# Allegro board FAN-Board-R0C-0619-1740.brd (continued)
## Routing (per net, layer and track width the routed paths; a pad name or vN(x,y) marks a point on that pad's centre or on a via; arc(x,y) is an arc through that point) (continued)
FAN2R_SENSOR: length 76.6
  TOP w0.203: BGA1.N7 v2(153.32,20.74) ; R23.2 v3(106.14,30.78)
  BOTTOM w0.203: v2(153.32,20.74) 149.9,24.16 137.52,24.16 132.44,19.08 120.24,19.08 117.73,21.59 98.42,21.59 97.61,22.41 97.61,24.31 100.14,26.85 104.32,26.85 106.67,29.2 v1(106.67,30.18) 106.67,30.25 v3(106.14,30.78)
FAN2R_SENSOR_R: length 25.3
  TOP w0.203: CONN5.1 105.4,34.49 106.13,33.76 v3(106.13,33.04) 106.14,33.03 R23.1 R24.1 ; U4.C1 v3(95.43,23.61)
  BOTTOM w0.203: v3(95.43,23.61) v1(95.43,24.4) 98.44,27.41 103.84,27.41 105.56,29.13 105.56,32.47 v3(106.13,33.04)
FAN3_DET: length 109.5
  TOP w0.152: BGA1.R10 150.14,22.33 150.14,23.37
  TOP w0.203: 150.14,23.37 150.14,23.65 149.22,24.56 142.1,24.56 134.28,16.74 98.25,16.74 87.36,27.62 56.2,27.62 53.96,29.86 v3(53.96,30.77) R10.2
  BOTTOM w0.203: v1(53.17,30.77) 53.95,30.77 v3(53.96,30.77)
FAN3_DET_R: length 36.2
  TOP w0.203: R114.1 R10.1 v3(53.96,33.08) ; U10.C1 v3(41.33,23.17)
  BOTTOM w0.203: v3(41.33,23.17) v1(41.33,23.98) 41.33,25.85 37.08,30.1 37.08,32.05 37.29,32.26 53.13,32.26 v3(53.96,33.08) 54.68,33.81 CONN4.16
FAN3_DIR: length 114.4
  TOP w0.203: BGA1.P10 v2(150.13,21.54) ; R9.2 v3(47.04,30.79)
  BOTTOM w0.203: v3(47.04,30.79) 47.35,31.1 v1(49.52,31.1) 53.36,27.25 53.36,24.49 58.67,19.18 118.07,19.18 119.61,17.64 133.21,17.64 138.43,22.86 148.81,22.86 v2(150.13,21.54)
FAN3_DIR_R: length 17.5
  TOP w0.203: U10.C2 43.23,28.24 45.59,30.61 45.59,32.13 45.83,32.37 R110.1 R9.1 v3(47.04,33.05)
  BOTTOM w0.203: v1(47.83,33.05) 47.04,33.05 v3(47.04,33.05) 47.06,33.07 CONN4.13
FAN3_IN_PWM: length 18.4
  TOP w0.203: U12.C2 v3(39.75,24.89) 39.75,25.52 39.75,25.53 39.75,26.42 43.62,30.29 44.44,30.29 45.09,30.94 45.09,32.16 44.88,32.37 R22.2 44.5,38.42 CONN4.4
  BOTTOM w0.203: v1(39.75,25.7) v3(39.75,24.89)
FAN3_LED_G: length 154.1
  TOP w0.152: BGA1.P11 149.33,21.54 149.33,23.01 148.97,23.37
  TOP w0.203: R1.2 11.68,34.04 v3(12.45,33.27) 20.04,25.68 30.39,25.68 38.54,17.53 57.22,17.53 58.82,15.93 134.97,15.93 142.79,23.75 148.59,23.75 148.97,23.37
  BOTTOM w0.203: v1(13.97,32.51) 13.21,32.51 v3(12.45,33.27)
FAN3_LED_G_R: length 4.2
  TOP w0.203: R1.1 11.77,37.17 v3(11.77,38.1) LED1.C2
  BOTTOM w0.203: v1(11.94,37.08) 11.94,37.94 v3(11.77,38.1)
FAN3_LED_R: length 152.9
  TOP w0.203: BGA1.T11 149.74,22.76 149.74,23.21 148.79,24.16 142.5,24.16 134.67,16.33 58.99,16.33 57.39,17.93 38.96,17.93 30.35,26.54 21.46,26.54 v3(13.72,34.29) ; R5.2 v3(9.65,34.29)
  BOTTOM w0.203: v3(13.72,34.29) v1(12.7,34.29) v3(9.65,34.29)
FAN3_LED_R_R: length 5
  TOP w0.203: R5.1 10.02,37.46 v3(10.02,38.1) LED1.C1
  BOTTOM w0.203: v1(9.91,37.08) 9.91,37.98 v3(10.02,38.1)
FAN3_OUT_PWM: length 17.2
  TOP w0.203: U12.C1 v3(37.85,24.89) 37.85,26.55 41.49,30.19 41.49,32.03 41.83,32.37 R21.2 42.09,32.99 41.98,33.09 CONN4.3
  BOTTOM w0.203: v1(37.85,25.7) v3(37.85,24.89)
FAN3_PWM: length 123.6
  TOP w0.203: v3(42.09,30.78) R21.1 R22.1 ; BGA1.M9 v2(150.93,19.94)
  BOTTOM w0.203: v3(42.09,30.78) v1(42.65,31.34) 43.14,31.84 50.12,31.84 54.58,27.38 54.58,26.41 56.86,24.13 58.9,24.13 62.46,20.57 117.54,20.57 119.95,18.16 132.96,18.16 135.37,20.57 135.39,20.57 138.11,23.29 149.17,23.29 150.93,21.54 v2(150.93,19.94)
FAN3_SENSOR: length 120.4
  TOP w0.203: v3(39.83,30.78) R19.2 ; BGA1.N10 v2(150.13,20.74)
  BOTTOM w0.203: v3(39.83,30.78) v1(39.83,29.99) 41.43,28.4 48.37,28.4 53.59,23.18 53.59,21.65 56.48,18.77 117.9,18.77 119.44,17.23 133.58,17.23 137.12,20.78 146.94,20.78 147.47,21.31 149.56,21.31 v2(150.13,20.74)
FAN3_SENSOR_R: length 18.1
  TOP w0.203: R19.1 R20.1 ; R19.1 39.83,32.91 39.44,33.3 CONN4.2 ; R19.1 39.54,32.37 39.28,32.11 39.28,28.93 36.24,25.89 v3(36.24,24.89) U11.C2
  BOTTOM w0.203: v1(36.24,25.7) v3(36.24,24.89)
FAN3_VCP: length 3.7
  TOP w0.203: U1.4 64.03,25.71 C8.2 v3(65.33,25.09)
  BOTTOM w0.203: v1(64.52,25.09) v3(65.33,25.09)
FAN3R_SENSOR: length 121.6
  TOP w0.203: BGA1.M11 v2(149.33,19.94) ; R17.2 v3(37.63,30.78)
  BOTTOM w0.203: v3(37.63,30.78) 37.63,30.66 v1(38.17,30.12) 40.45,27.84 47.85,27.84 51.99,23.7 51.99,21.22 54.85,18.36 117.74,18.36 119.37,16.73 134.46,16.73 137.06,19.33 148.72,19.33 v2(149.33,19.94)
FAN3R_SENSOR_R: length 18
  TOP w0.203: R17.1 R18.1 ; R17.1 37.63,33.72 36.9,34.45 CONN4.1 ; R17.1 37.47,32.37 37.09,31.99 37.09,29.09 34.34,26.34 v3(34.34,24.89) U11.C1
  BOTTOM w0.203: v1(34.34,25.7) v3(34.34,24.89)
FAN4_DET: length 116.2
  TOP w0.203: R16.2 v3(259.41,30.79) ; BGA1.N3 v2(156.52,20.74)
  BOTTOM w0.203: v3(259.41,30.79) 259.39,30.79 258.57,29.97 v1(252.48,29.97) 249.43,29.97 239.49,20.03 211.92,20.03 204.4,27.55 194.61,27.55 187.5,20.45 165.54,20.45 163.51,22.48 160.4,22.48 158.88,20.95 156.74,20.95 v2(156.52,20.74)
FAN4_DET_R: length 33.3
  TOP w0.203: U13.C1 v3(239.35,20.87) ; R115.1 R16.1 v3(259.41,33.05)
  BOTTOM w0.203: v3(239.35,20.87) v1(240.05,21.57) 249.09,30.61 251.76,30.61 253.01,31.85 258.21,31.85 v3(259.41,33.05) 260.18,33.83 CONN7.16
FAN4_DIR: length 106.1
  TOP w0.152: 157.95,18.35 155.73,18.35 BGA1.K4
  TOP w0.203: 157.95,18.35 168.49,18.35 171.42,15.42 205.43,15.42 215.74,25.73 244.32,25.73 249.35,30.76 251.17,30.76 v3(251.88,31.46) R15.2
  BOTTOM w0.203: v3(251.88,31.46) 251.52,31.82 v1(251.16,31.82)
FAN4_DIR_R: length 26.5
  TOP w0.203: v3(252.57,33.05) R15.1 R111.1 253.86,32.37 254,32.23 254,30.48 253.75,30.23 249.72,30.23 U13.C2
  BOTTOM w0.203: v1(251.77,33.05) v3(252.57,33.05) 252.56,33.05 CONN7.13
FAN4_IN_PWM: length 25
  TOP w0.203: R40.2 v3(250,33.04) 250.02,33.07 CONN7.4 ; U15.C2 v3(237.74,20.85)
  BOTTOM w0.203: v3(250,33.04) 250,32.45 241.05,23.5 239.78,23.5 238.3,22.02 v1(238.3,21.41) v3(237.74,20.85)
FAN4_LED_G: length 73.2
  TOP w0.152: 157.93,20.76 157.31,20.76 BGA1.P2
  TOP w0.203: v1(217.42,35.56) v3(217.42,34.54) 217.42,31.9 203.47,17.95 172.22,17.95 168.26,21.91 159.08,21.91 157.93,20.76
  BOTTOM w0.203: v1(217.42,35.56) v3(217.42,34.54)
FAN4_LED_G_R: length 4.3
  TOP w0.203: v1(217.42,37.08) 217.27,37.23 v3(217.27,38.1) LED4.C2
  BOTTOM w0.203: v1(217.42,37.08) 217.42,37.95 v3(217.27,38.1)
FAN4_LED_R: length 69.9
  TOP w0.203: BGA1.R1 158.13,22.35 168.66,22.35 172.43,18.58 202.68,18.58 215.39,31.29 v3(215.39,34.54) v1(215.39,35.56)
  BOTTOM w0.203: v1(215.39,35.56) v3(215.39,34.54)
FAN4_LED_R_R: length 4.9
  TOP w0.203: v1(215.39,37.08) 215.52,37.22 v3(215.52,38.1) LED4.C1
  BOTTOM w0.203: v3(215.52,38.1) 215.39,37.97 v1(215.39,37.08)
FAN4_OUT_PWM: length 24.8
  TOP w0.203: R39.2 247.46,32.99 v3(247.41,33.04) 247.48,33.12 CONN7.3 ; U15.C1 v3(235.84,20.85)
  BOTTOM w0.203: v3(247.41,33.04) 246.86,32.49 246.86,30.43 240.56,24.13 239.12,24.13 v1(236.4,21.41) v3(235.84,20.85)
FAN4_PWM: length 102.1
  TOP w0.152: 158.31,19.05 158.2,19.15 157.32,19.15 BGA1.M2
  TOP w0.203: 158.31,19.05 158.43,18.92 168.83,18.92 171.73,16.03 205.16,16.03 215.44,26.31 242.99,26.31 v3(247.46,30.78) R39.1 R40.1
  BOTTOM w0.203: v1(248.03,31.35) v3(247.46,30.78)
FAN4_SENSOR: length 98
  TOP w0.152: 158.31,19.94 156.52,19.94 BGA1.M3
  TOP w0.203: 158.31,19.94 158.75,19.49 169.02,19.49 171.84,16.68 204.88,16.68 215.07,26.87 241.33,26.87 v3(245.24,30.78) R37.2
  BOTTOM w0.203: v1(245.32,29.98) 245.24,30.06 v3(245.24,30.78)
FAN4_SENSOR_R: length 26.2
  TOP w0.203: R38.1 R37.1 245.24,33.01 v3(245.21,33.04) 244.94,33.3 CONN7.2 ; U14.C2 v3(234.28,20.85)
  BOTTOM w0.203: v3(234.28,20.85) v1(234.28,21.65) 237.65,25.02 240.03,25.02 244.68,29.67 244.68,32.51 v3(245.21,33.04)
FAN4_VCP: length 3.9
  TOP w0.203: v3(250.58,2.43) C52.2 251.2,3.73 U17.4
  BOTTOM w0.203: v3(250.58,2.43) 250.06,2.95 v1(250.06,3.2)
FAN4R_SENSOR: length 95.4
  TOP w0.203: R35.2 v3(243.14,30.78) 243.14,29.68 240.84,27.38 214.72,27.38 204.67,17.34 172.05,17.34 167.88,21.5 159.61,21.5 158.46,20.34 BGA1.N1
  BOTTOM w0.203: v1(243.67,30.15) 243.14,30.67 v3(243.14,30.78)
FAN4R_SENSOR_R: length 27.2
  TOP w0.203: U14.C1 v3(232.38,20.85) ; CONN7.1 242.4,34.46 243.13,33.73 v3(243.13,33.04) 243.14,33.03 R35.1 R36.1
  BOTTOM w0.203: v3(232.38,20.85) v1(232.38,21.65) 232.38,22.86 235.18,25.65 239.09,25.65 242.57,29.13 242.57,32.48 v3(243.13,33.04)
FAN_IDLE: length 120.6
  TOP w0.203: BGA1.A11 149.72,10.36 149.49,10.12 v2(149.49,9.89) ; R59.2 v3(60.1,8.38) 60.1,7.11 60.07,7.08 60.07,7.05 57.78,4.76 55.47,4.76 54.7,5.52 54.7,6.79 53.5,8 51.42,8 50.48,7.06 CONN1.21
  BOTTOM w0.203: v2(149.49,9.89) 148.62,9.02 142.72,9.02 141.8,8.1 138.96,8.1 138.94,8.13 135.02,8.13 133.13,10.02 133.13,13.27 131.13,15.27 91.33,15.27 83.61,7.54 79.6,7.54 78.84,6.78 72.31,6.78 68.99,10.11 63.02,10.11 v1(61.38,8.47) 61.29,8.38 v3(60.1,8.38)
FAN_INTERRUPT: length 129.5
  TOP w0.203: BGA1.B13 v2(147.73,11.15) ; CONN1.19 v3(47.94,8.22) ; v3(134.42,9.91) 134.06,9.55 134.06,4.22 132.66,2.82 100.82,2.82 100.3,3.34 83.38,3.34 81.08,5.63 v3(81.08,10.26)
  BOTTOM w0.203: v3(47.94,8.22) v1(47.94,9.01) 46.83,10.12 46.83,14.86 47.47,15.49 48.23,15.49 54.25,9.47 60.43,9.47 62.27,11.32 80.02,11.32 v3(81.08,10.26) ; v2(147.73,11.15) 146.94,11.15 146.25,11.84 142.57,11.84 139.67,8.94 136.14,8.94 135.18,9.91 v3(134.42,9.91)
FAN_SCL_1: length 173.1
  TOP w0.203: CONN1.12 37.78,9.72 38.59,8.9 54.12,8.9 56.24,6.79 v3(56.24,5.58) ; R94.1 150.5,3.32 v3(150.81,3.63) 150.79,3.66 R84.1
  BOTTOM w0.203: R103.1 v3(56.24,5.58) v1(57.45,5.58) 57.87,5.58 60.99,2.46 83.23,2.46 84.48,3.71 100.56,3.71 102.24,2.03 149.21,2.03 v3(150.81,3.63) 150.81,2.98 151.67,2.12 164.59,2.12 165.14,2.67 194.84,2.67 195.34,3.17 R105.1
FAN_SCL_1_R: length 8.3
  TOP w0.152: 151.17,10.22 151.17,10.31 150.94,10.54 150.94,12.76 BGA1.D9
  TOP w0.203: 151.17,10.22 151.17,9.19 150.79,8.8 v3(150.79,6.87) R84.2
  BOTTOM w0.203: v1(150.94,7.67) 150.79,7.51 v3(150.79,6.87)
FAN_SDA_1: length 174.5
  TOP w0.203: CONN1.10 v3(35.24,14.08) ; R95.1 153.91,3.43 v3(154.13,3.64) R89.1
  BOTTOM w0.203: R100.1 176.03,6.55 172.93,3.44 154.33,3.44 v3(154.13,3.64) 154.11,3.63 153.2,3.63 152.87,3.96 151.61,3.96 151.29,4.28 150.42,4.28 149.83,3.7 148.23,3.7 147.26,2.73 102.4,2.73 100.81,4.32 84.23,4.32 82.98,3.07 61.24,3.07 55.92,8.39 R99.1 52.61,8.39 51.8,7.58 47.68,7.58 46.11,9.14 40.96,9.14 v1(36.03,14.08) v3(35.24,14.08)
FAN_SDA_1_R: length 11.4
  TOP w0.152: 153.54,10.22 153.33,10.44 153.33,14.13 153.11,14.35 152.52,14.35 BGA1.F8
  TOP w0.203: R89.2 v3(154.13,6.87) 154.13,9.46 153.54,10.04 153.54,10.22
  BOTTOM w0.203: v1(154.13,8.37) v3(154.13,6.87)
FANCARD_CPLD_TCK: length 27.1
  TOP w0.203: CONN1.17 45.4,3.02 45.81,2.6 54.07,2.6 55.66,4.19 57.87,4.19 58.28,4.6 63.22,4.6 v3(66.28,7.66) U16.4
  BOTTOM w0.203: v1(67.09,7.66) v3(66.28,7.66)
FANCARD_CPLD_TCK_Y: length 97.3
  TOP w0.203: v2(153.12,4.55) R86.2 ; R91.1 v3(132.59,6.1) 132.59,12.45 129.51,15.52 81.2,15.52 78.44,12.75 78.44,8.15 77.27,6.99 74.49,6.99 74.47,7.01 U16.16
  BOTTOM w0.203: v3(132.59,6.1) v1(132.59,5.3) 135.1,5.3 136.41,4 144.02,4 145.43,5.41 152.25,5.41 v2(153.12,4.55)
FANCARD_CPLD_TDI: length 35.3
  TOP w0.203: U16.6 v3(68.64,6.36) 68.64,9.84 66.04,12.45 61.04,12.45 57.02,16.46 46.96,16.46 45.38,14.88 45.38,11.78 CONN1.18
  BOTTOM w0.203: v1(69.45,6.36) v3(68.64,6.36)
FANCARD_CPLD_TDI_Y: length 104.3
  TOP w0.203: R87.2 v3(155.15,4.5) ; U16.14 72.44,5.7 72.08,5.34 72.08,3.52 72.52,3.07 74.68,3.07 79.58,7.98 79.58,10.31 81.2,11.94 88.98,11.94 v3(89.51,11.4) 89.52,11.39 R61.1 90.36,11.38 CONN3.3
  BOTTOM w0.203: v3(155.15,4.5) 153.83,5.82 145.28,5.82 144.89,6.2 143.41,6.2 143,5.79 134.93,5.79 131.91,8.81 131.91,12.59 130.45,14.05 92.63,14.05 v1(90.36,11.77) 89.99,11.4 v3(89.51,11.4)
FANCARD_CPLD_TDO: length 39.4
  TOP w0.203: CONN1.16 42.86,13.89 45.97,16.99 57.18,16.99 61.21,12.95 66.12,12.95 70.76,8.31 U16.18 v3(74.47,8.31)
  BOTTOM w0.203: v1(75.28,8.31) v3(74.47,8.31)
FANCARD_CPLD_TDO_Y: length 108.4
  TOP w0.203: U16.2 v3(66.28,8.96) ; R88.2 v3(156.17,4.5) ; CONN3.2 v3(87.82,7.62)
  BOTTOM w0.203: v3(156.17,4.5) 154.44,6.23 145.53,6.23 145.09,6.68 143.25,6.68 142.77,6.2 135.1,6.2 132.32,8.98 132.32,12.9 130.76,14.45 91.67,14.45 87.82,10.6 v3(87.82,7.62) 87.82,7.11 85.64,4.93 72.14,4.93 68.11,8.96 v1(67.23,8.96) v3(66.28,8.96)
FANCARD_CPLD_TMS: length 29
  TOP w0.203: U16.8 v3(66.28,5.05) 65.41,4.19 58.45,4.19 57.94,3.68 55.78,3.68 54.26,2.16 43.67,2.16 42.86,2.97 CONN1.15
  BOTTOM w0.203: v1(67.09,5.05) v3(66.28,5.05)
FANCARD_CPLD_TMS_Y: length 90.4
  TOP w0.203: U16.12 75.29,4.4 79.07,8.19 79.07,10.62 80.8,12.34 95.28,12.34 96.24,11.38 v3(96.27,11.38) R62.1 ; R85.2 v2(152.11,4.55)
  BOTTOM w0.203: v2(152.11,4.55) 151.66,5 145.65,5 144.03,3.38 135.91,3.38 134.47,4.83 132.97,4.83 132.84,4.69 132.34,4.69 132.2,4.83 101.53,4.83 96.95,9.4 v1(96.95,10.49) 96.95,10.69 v3(96.27,11.38)
FANCARD_RST_N: length 128.7
  TOP w0.203: v3(80.34,9.93) 80.34,5.8 83.21,2.93 100.13,2.93 100.65,2.41 132.84,2.41 134.49,4.06 134.49,8.76 v3(134.85,9.12) ; CONN1.20 v3(47.94,14.8) 47.94,15.34 R57.2 ; BGA1.B3 v2(155.73,11.15)
  BOTTOM w0.203: v3(80.34,9.93) 79.36,10.91 62.53,10.91 60.68,9.07 52.88,9.07 v1(47.94,14.01) v3(47.94,14.8) ; v2(155.73,11.15) 149.17,11.15 147.68,9.65 141.02,9.65 140.38,9.01 140.32,9.01 139.84,8.53 135.43,8.53 v3(134.85,9.12)
ILIM_FAN1: length 3.5
  TOP w0.203: U3.5 202.57,26.21 R45.2 v3(203.38,26.09)
  BOTTOM w0.203: v1(204.19,26.09) v3(203.38,26.09)
ILIM_FAN2: length 3.5
  TOP w0.203: U2.5 133.04,26.21 R44.2 v3(133.85,26.09)
  BOTTOM w0.203: v1(134.66,26.09) v3(133.85,26.09)
ILIM_FAN3: length 3.5
  TOP w0.203: U1.5 64.52,26.21 R43.2 v3(65.33,26.09)
  BOTTOM w0.203: v1(66.14,26.09) v3(65.33,26.09)
ILIM_FAN4: length 3.5
  TOP w0.203: v3(251.58,2.43) R93.2 251.7,3.23 U17.5
  BOTTOM w0.203: v3(251.58,2.43) 251.58,2.93 v1(251.33,3.18)
JTAG_TCK_R: length 32.5
  TOP w0.203: CONN3.8 104.82,3.28 130.35,3.28 R90.1 R91.2 v3(132.59,3.82)
  BOTTOM w0.203: v1(131.78,3.82) v3(132.59,3.82)
JTAG_TMS_R: length 8.7
  TOP w0.203: CONN3.6 97.98,11.04 R62.2 R63.1 v3(98.99,12.14)
  BOTTOM w0.203: v1(99.8,11.73) 99.39,12.14 v3(98.99,12.14)
SST_FAN1: length 2.4
  TOP w0.203: v3(197.76,26.75) U3.6
  BOTTOM w0.203: v3(197.76,26.75) 197.76,26.06 C7.2 v1(197.64,24.92)
SST_FAN2: length 2.5
  TOP w0.203: v3(128.23,26.75) U2.6
  BOTTOM w0.203: v1(128.72,25.06) 128.13,25.65 C6.2 128.13,26.65 v3(128.23,26.75)
SST_FAN3: length 2.8
  TOP w0.203: U1.6 v3(59.71,26.91)
  BOTTOM w0.203: v1(60.35,25.12) 59.6,25.87 C5.2 59.6,26.8 v3(59.71,26.91)
SST_FAN4: length 2.2
  TOP w0.203: v3(252.23,8.04) U17.6
  BOTTOM w0.203: C42.2 252.45,8.26 v3(252.23,8.04) v1(251.45,8.04)
TEMP_SENSOR_ALERT_1: length 62
  TOP w0.152: BGA1.H11 v2(149.33,16.74)
  BOTTOM w0.203: U18.3 198.97,6.93 199.53,7.49 R96.2 199.53,10.53 v1(199.52,10.54) 199.53,10.56 199.53,11.54 192.09,18.99 159.96,18.99 155.89,14.92 154.49,14.92 153.83,15.59 153.83,16.15 153.47,16.51 151.08,16.51 150.85,16.74 v2(149.33,16.74)
TEMP_SENSOR_ALERT_2: length 110.5
  TOP w0.152: BGA1.J13 147.72,17.55 145.44,17.55
  TOP w0.203: v3(56.25,2.72) 56.45,2.53 99.96,2.53 100.48,2.01 133.05,2.01 135.43,4.39 135.43,15.16 139.83,19.56 143.43,19.56 145.44,17.55
  BOTTOM w0.203: v3(56.25,2.72) 56.25,3.49 R106.2 56.16,3.58 v1(55.2,3.58) 54.58,4.21 U19.3
VERSION_ID_1: length 40.7
  TOP w0.152: 158.31,15.95 157.33,15.95 BGA1.G2
  TOP w0.203: R77.1 R78.2 v3(188.47,7.51) ; 158.31,15.95 159.33,15.95 v3(159.7,16.32)
  BOTTOM w0.203: v3(159.7,16.32) 159.7,17.4 160.78,18.48 178.31,18.48 v1(188.47,8.32) v3(188.47,7.51)
VERSION_ID_2: length 37.1
  TOP w0.152: BGA1.G3 156.53,15.14 158.31,15.14
  TOP w0.203: v3(185.55,7.51) R76.2 R75.1 ; 158.31,15.14 160.82,15.14 v3(160.97,14.99)
  BOTTOM w0.203: v3(160.97,14.99) 162.88,16.89 176.97,16.89 v1(185.55,8.32) v3(185.55,7.51)
VERSION_ID_3: length 31.1
  TOP w0.203: R70.2 R69.1 v3(175.32,7.51) ; BGA1.F5 v2(154.92,14.35)
  BOTTOM w0.203: v1(175.32,8.29) v3(175.32,7.51) 173.02,5.21 162.75,5.21 158.69,9.27 158.69,13.27 157.61,14.35 v2(154.92,14.35)
VSTB_3V3: length 101.3
  TOP w0.381: BGA1.M13 v2(147.73,19.94) ; BGA1.D12 v2(148.53,12.75) ; U16.20 76.07,9.61 C43.1 v3(76.08,10.29) ; BGA1.N5 v2(154.92,20.74) ; R115.2 v3(258.44,30.79) ; R112.2 v3(189.99,30.79) ; BGA1.T1 v2(157.33,22.35) ; BGA1.G7 v2(153.32,15.15) ; R18.2 v3(38.67,30.73) ; BGA1.J10 v2(150.13,17.54) ; R68.1 v3(77.85,8.33) ; R80.1 v3(146.34,4.45) ; BGA1.A1 v2(157.33,11.14) ; BGA1.K9 v2(150.93,18.34) ; BGA1.K8 v2(152.52,18.34) ; C44.1 v3(162.92,6.41) ; v3(100.69,11.38) R63.2 ; R24.2 v3(107.19,30.78) ; R26.2 v3(109.35,30.78) ; R78.1 v3(188.47,4.31) ; BGA1.E4 v2(155.72,13.55) ; R74.1 v3(182.63,4.31) ; C31.1 v3(142.75,16.76) ; CONN1.6 v3(30.16,9.4) ; R82.1 v3(148.44,4.45) ; R20.2 v3(40.89,30.73) ; BGA1.J7 v2(153.32,17.54) ; R76.1 v3(185.55,4.31) ; v3(53.34,29.84) 52.96,30.23 R114.2 ; R32.2 v3(177.74,30.78) ; C26.1 v3(142.75,18.8) ; R36.2 v3(244.16,30.78) ; C47.1 v3(142.88,7.12) ; CONN3.1 84.87,7.5 C51.2 v3(82.17,8.18) ; CONN1.5 v3(30.16,7.33) ; BGA1.A16 v2(145.72,10.19) ; R59.1 59.58,11.95 v3(59.27,12.26) ; BGA1.K7 v2(153.32,18.34) ; R72.1 v3(179.71,4.31) ; BGA1.N12 v2(148.53,20.74) ; BGA1.G8 v2(152.52,15.15) ; v3(149.23,4.48) 149.45,4.7 R83.1 ; BGA1.M4 v2(155.72,19.94) ; BGA1.H10 v2(150.13,15.95) ; R70.1 v3(176.78,4.31) ; LED1.A v3(13.52,38.99) ; BGA1.K10 v2(150.13,18.34) ; v3(92.05,11.37) 92.02,11.39 R61.2 ; v3(148.46,2.79) R94.2 ; BGA1.G10 v2(150.13,15.15) ; LED4.A v3(219.02,38.87) ; BGA1.D5 v2(154.92,12.75) ; LED2.A v3(82.02,38.94) ; R113.2 v3(121.54,30.61) ; v3(136.27,9.61) C46.1 L8.2 ; R81.1 v3(147.36,4.45) ; R66.1 v3(64.02,8.69) ; R108.2 v3(184.91,30.79) ; R111.2 v3(253.49,30.79) ; C29.1 v3(142.75,17.78) ; BGA1.H7 v2(153.32,15.95) ; R57.1 v3(50.29,15.62) ; BGA1.T16 v2(146.12,22.35) ; R95.2 v3(155.96,2.79) ; R38.2 v3(246.25,30.78) ; LED3.A v3(150.52,38.96) ; C50.1 v3(161.1,7.8) ; BGA1.G9 v2(150.93,15.15) ; CONN1.4 v3(27.62,9.4) ; R109.2 v3(114.68,30.61) ; CONN1.3 v3(27.62,7.33) ; R30.2 v3(175.64,30.78) ; BGA1.E13 v2(147.73,13.55) ; R110.2 v3(46.1,30.74) ; C48.1 v3(144.59,7.8)
  TOP w0.508: C30.1 v3(32.02,14.83) ; C33.1 v3(29.76,15.55)
  BOTTOM w0.381: v2(147.73,13.55) 147.73,13.59 147.35,13.97 C28.1 ; R119.2 v3(207.14,6.6) ; v2(157.33,11.14) 157.62,10.85 C37.1 ; v2(148.53,12.75) 148.53,12.75 C32.1 ; v3(92.05,11.37) 92.04,11.35 v1(92.04,10.32) ; v2(153.32,18.34) 153.39,18.27 C2.1 ; R97.1 v3(207.14,8.38) ; C24.1 152.52,14.46 v2(152.52,15.15) ; C1.1 152.26,18.08 v2(152.52,18.34) ; v3(58.61,3.58) 58.58,3.56 R106.1 ; C4.1 154.7,12.53 v2(154.92,12.75) ; U19.8 v3(49.23,6.16) ; R47.1 v3(125.96,26.61) ; C49.1 146.03,22.26 v2(146.12,22.35) ; v2(150.93,15.15) 151.09,14.99 C3.1 ; v3(197.49,9.17) R96.1 ; v2(155.72,13.55) 156.53,13.55 C25.1 ; R104.1 v3(44.45,5.71) ; R46.1 v3(57.45,26.62) ; R64.1 v3(252.96,9.6) ; v1(146.63,10.41) 146.41,10.19 v2(145.72,10.19) 145.61,10.3 C39.1 ; v2(150.13,15.95) 150.12,15.94 C36.1 ; C34.1 155.55,20.11 v2(155.72,19.94) ; v2(150.93,18.34) 150.97,18.39 C11.1 ; v1(202.84,4.04) 202.84,5.01 v3(202.82,5.03) U18.8 ; v2(150.13,18.34) 149.91,18.12 C20.1 ; R102.2 v3(207.14,4.83) ; R48.1 v3(195.5,26.62) ; v2(157.33,22.35) 157.46,22.48 C19.1 ; R116.2 v3(44.45,7.49) ; v2(147.73,19.94) 147.64,20.03 C40.1 ; R107.2 v3(44.45,3.94)
  vias: v1(34.77,19.1) v1(57.4,14.03)
VSTB_3V3_25M_VCC: length 5.9
  TOP w0.203: C45.1 R65.1 138.86,5.74 138.51,6.09 OSC1.4 137.62,6.84 137.6,6.82 L8.1 v3(136.14,6.82)
  BOTTOM w0.203: v1(135.33,6.82) v3(136.14,6.82)
N66403123: length 14.9
  TOP w0.381: R79.2 115.03,7.51 ; R58.2 112.38,10.16
  BOTTOM w0.381: H7.3 v1(107.44,12.78)
N66410905: length 3.9
  BOTTOM w0.203: U18.2 199.17,6.28 199.46,5.99 v1(199.46,4.32) 199.46,4.31 R105.2
N66410909: length 2.2
  BOTTOM w0.203: R100.2 v1(197.2,5.64) 197.21,5.63 U18.1
N66410919: length 2.8
  BOTTOM w0.203: U19.2 54.44,4.86 54.44,4.86 R103.2 v1(55.33,5.87)
N66410923: length 2.1
  BOTTOM w0.203: R99.2 53.82,6.5 v1(53.77,6.45) 53.58,6.26 U19.1
N66487659: length 4.8
  TOP w0.203: v3(76.28,7.49) 76.08,7.69 R68.2 75.62,8.33 74.99,8.96 U16.19
  BOTTOM w0.203: v1(77.09,7.49) v3(76.28,7.49)
N66707807: length 8.3
  TOP w0.152: 149.06,10.22 149.32,10.48 149.32,11.73 149.54,11.95 150.13,11.95 BGA1.C10
  TOP w0.203: R82.2 v3(148.44,6.78) 148.44,9.6 149.06,10.22
  BOTTOM w0.203: v1(148.63,7.58) 148.44,7.38 v3(148.44,6.78)
N66707810: length 7.4
  TOP w0.152: 150.11,10.22 150.11,11.13 BGA1.B10
  TOP w0.203: 150.11,10.22 150.11,9.78 149.45,9.12 v3(149.45,6.78) R83.2
  BOTTOM w0.203: v1(149.76,8.17) 149.76,7.09 v3(149.45,6.78)
N66708102: length 6.2
  TOP w0.203: BGA1.A13 146.34,8.96 v3(146.34,6.78) R80.2
  BOTTOM w0.203: v1(145.78,7.34) v3(146.34,6.78)
N66708112: length 7.7
  TOP w0.152: 148.4,10.22 148.54,10.36 148.54,11.93 BGA1.C13
  TOP w0.203: 148.4,10.22 147.36,9.18 v3(147.36,6.78) R81.2
  BOTTOM w0.203: v1(147.36,7.57) v3(147.36,6.78)
N66771338: length 10.9
  TOP w0.152: 151.8,10.22 151.8,10.41 151.73,10.48 151.73,11.14 BGA1.B9
  TOP w0.203: 151.8,10.22 151.8,8.8 151.45,8.45 151.45,4.21 151.97,3.69 152.27,3.69 v2(152.61,3.35) 152.21,2.95 TP16.1
  BOTTOM w0.203: v2(152.61,3.35) 152.46,3.2 v1(151.72,3.2)
N66771341: length 11.9
  TOP w0.203: TP15.1 v3(146.81,3.62) 149.34,3.62 150.11,4.39 150.11,9.02 150.52,9.43 BGA1.A10
  BOTTOM w0.203: v1(146.02,3.62) v3(146.81,3.62)
N66771344: length 12
  TOP w0.203: BGA1.F10 v2(150.13,14.35) ; TP10.1 v3(141.54,12.45)
  BOTTOM w0.203: v3(141.54,12.45) v1(142.33,12.45) 147.19,12.45 147.45,12.19 149.73,12.19 150.13,12.59 v2(150.13,14.35)
N66771524: length 12.3
  TOP w0.203: BGA1.F12 v2(148.53,14.35) ; TP9.1 v3(138.81,12.45)
  BOTTOM w0.203: v3(138.81,12.45) 139.27,12.45 v1(139.55,12.16) 140.13,12.16 141.35,13.39 143.08,13.39 144.27,14.58 148.3,14.58 v2(148.53,14.35)
N66771539: length 12.6
  TOP w0.203: BGA1.G11 v2(149.33,15.15) ; TP3.1 v3(138.81,15.56)
  BOTTOM w0.203: v3(138.81,15.56) v1(139.37,16.12) 139.49,16.23 143.38,16.23 144.46,15.15 v2(149.33,15.15)
N66771544: length 9.5
  TOP w0.152: 145.52,14.35 146.68,14.35 147.07,14.74 BGA1.F14
  TOP w0.203: TP8.1 v3(140.02,13.4) 144.57,13.4 145.52,14.35
  BOTTOM w0.203: v1(139.21,13.4) v3(140.02,13.4)
N66771549: length 6.1
  TOP w0.203: BGA1.F16 145.24,14.74 144.65,14.16 v3(141.54,14.16) TP7.1
  BOTTOM w0.203: v1(142.35,14.16) v3(141.54,14.16)
N66771572: length 7.7
  TOP w0.152: BGA1.G14 146.93,15.94 145.54,15.94
  TOP w0.203: 145.54,15.94 141.92,15.94 v3(141.54,15.56) TP4.1
  BOTTOM w0.203: v1(142.35,15.56) v3(141.54,15.56)
N66771573: length 8.5
  TOP w0.152: 145.35,15.14 146.12,15.14 BGA1.G15
  TOP w0.203: TP6.1 v3(140.02,14.8) 142.75,14.8 143.09,15.14 145.35,15.14
  BOTTOM w0.203: v1(139.21,14.8) v3(140.02,14.8)
N66771601: length 14.3
  TOP w0.152: 158.31,17.55 154.92,17.55 BGA1.K5
  TOP w0.203: TP1.1 167.28,17.65 167.27,17.65 v3(162.5,17.65) 162.39,17.55 158.31,17.55
  BOTTOM w0.203: v3(162.5,17.65) 162.56,17.72 v1(163.58,17.72)
N66771603: length 9.5
  TOP w0.203: v3(161.16,20.89) 161.73,20.32 TP2.1 ; BGA1.L4 v2(155.72,19.14)
  BOTTOM w0.203: v3(161.16,20.89) 160.15,20.89 v1(159.96,20.7) 159.58,20.32 158.62,20.32 157.44,19.14 v2(155.72,19.14)
N66771664: length 11
  TOP w0.152: BGA1.C2 157.34,11.93 158.31,11.93
  TOP w0.203: TP13.1 v3(158.05,5.14) 158.05,6.92 159.19,8.06 159.19,11.37 158.63,11.93 158.31,11.93
  BOTTOM w0.203: v1(158.05,4.33) v3(158.05,5.14)
N66771666: length 7.7
  TOP w0.203: TP11.1 v3(157.29,6.79) 158.75,8.26 158.75,11.02 158.22,11.54 BGA1.B1
  BOTTOM w0.203: v1(157.29,5.98) v3(157.29,6.79)
N66771757: length 12.2
  TOP w0.152: 158.31,12.76 157.31,12.76 BGA1.D2
  TOP w0.203: 158.31,12.76 159.14,12.76 160.08,11.81 160.08,7.37 159.64,6.92 v3(159.64,5.14) TP14.1
  BOTTOM w0.203: v1(159.64,4.33) v3(159.64,5.14)
N66771759: length 9
  TOP w0.152: BGA1.C1 158.31,12.34
  TOP w0.203: TP12.1 v3(158.81,6.79) 159.64,7.62 159.64,11.62 158.91,12.34 158.31,12.34
  BOTTOM w0.203: v1(158.81,5.98) v3(158.81,6.79)
N66771796: length 6.7
  TOP w0.203: TP5.1 v3(161.16,16.31) 160.4,15.54 BGA1.G1
  BOTTOM w0.203: v1(161.16,17.21) v3(161.16,16.31)
N66862681: length 4.3
  BOTTOM w0.203: U19.5 48.31,3.56 v1(47.94,3.19) 47.8,3.05 R117.2 R107.1
N66863023: length 4.3
  BOTTOM w0.203: U19.6 49.22,4.22 48.22,4.22 v1(47.94,4.5) 46.38,4.5 R118.2 R104.2
N66863106: length 4.8
  BOTTOM w0.203: R116.1 R101.2 v1(46.99,6.6) 48.36,5.23 48.36,5.22 48.5,5.09 48.5,5.09 48.73,4.86 U19.7
N66867929: length 3.8
  BOTTOM w0.203: U18.5 203.31,7.58 v1(204.11,8.39) 205.16,8.39 205.16,8.38 R97.2 R120.2
N66867942: length 3.6
  BOTTOM w0.203: R98.2 R119.1 204.44,6.6 v1(204.11,6.92) 204.11,6.93 U18.6
N66868149: length 4.1
  BOTTOM w0.203: R121.2 R102.1 204.75,4.83 v1(204.11,5.46) 204.11,5.57 203.41,6.28 U18.7

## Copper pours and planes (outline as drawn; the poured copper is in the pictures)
GND on TOP (solid shape): 1.65,31.37 2.02,30.5 1.96,29.56 2.05,28.96 1.96,28.36 2.05,27.76 1.96,27.16 2.02,26.21 1.65,25.34 1.65,23.28 1.02,23.28 1.02,25.57 1.4,26.32 1.28,27.16 1.42,27.76 1.28,28.36 1.42,28.96 1.28,29.56 1.4,30.39 1.02,31.14 1.02,38.1 1.65,38.1
GND on TOP (solid shape): 70.17,30.85 69.34,28.83 67.32,28 57.74,28 55.72,28.83 54.89,30.85 54.89,33.35 55.53,33.35 55.52,30.85 56.17,29.28 57.74,28.63 67.32,28.63 68.89,29.28 69.54,30.85 69.54,38.1 70.17,38.1
GND on TOP (solid shape): 138.67,30.85 137.84,28.83 135.82,28 126.24,28 124.23,28.83 123.39,30.85 123.39,33.27 124.03,33.27 124.03,30.85 124.67,29.28 126.24,28.63 135.82,28.63 137.39,29.28 138.04,30.85 138.04,38.1 138.67,38.1
GND on TOP (solid shape): 22.51,30.85 23.16,29.28 24.72,28.63 33.84,28.63 35.41,29.28 36.06,30.85 36.06,32.45 36.69,32.45 36.69,30.85 35.86,28.83 33.84,28 24.72,28 22.71,28.83 21.87,30.85 21.87,40.01 15.05,40.01 15.05,40.64 22.51,40.64
GND on TOP (solid shape): 91.01,30.85 91.66,29.28 93.22,28.63 102.34,28.63 103.91,29.28 104.56,30.85 104.56,32.51 105.19,32.51 105.19,30.85 104.36,28.83 102.34,28 93.22,28 91.21,28.83 90.37,30.85 90.37,40.01 83.31,40.01 83.31,40.64 91.01,40.64
GND on TOP (solid shape): 159.51,30.85 160.16,29.28 161.72,28.63 170.84,28.63 172.41,29.28 173.06,30.85 173.06,32.51 173.69,32.51 173.69,30.85 172.86,28.83 170.84,28 161.72,28 159.71,28.83 158.87,30.85 158.87,40.01 151.89,40.01 151.89,40.64 159.51,40.64
GND on TOP (solid shape): 207.17,30.85 206.34,28.83 204.32,28 194.74,28 192.72,28.83 191.89,30.85 191.89,32.96 191.89,33.21 192.53,33.21 192.52,30.85 193.17,29.28 194.74,28.63 204.32,28.63 205.89,29.28 206.54,30.85 206.54,38.23 207.17,38.23
GND on TOP (solid shape): 228.01,30.85 228.66,29.28 230.22,28.63 239.34,28.63 240.91,29.28 241.56,30.85 241.56,32.64 242.19,32.64 242.19,30.85 241.36,28.83 239.34,28 230.22,28 228.21,28.83 227.37,30.85 227.37,40.01 220.41,40.01 220.41,40.64 228.01,40.64
GND on TOP (solid shape): outline of 98 points within 1.02,1.02 261.03,33.34
GND on BOTTOM (solid shape): 1.65,31.37 2.02,30.5 1.96,29.56 2.05,28.96 1.96,28.36 2.05,27.76 1.96,27.16 2.02,26.21 1.65,25.34 1.65,23.28 1.02,23.28 1.02,25.57 1.4,26.32 1.28,27.16 1.42,27.76 1.28,28.36 1.42,28.96 1.28,29.56 1.4,30.39 1.02,31.14 1.02,38.1 1.65,38.1
GND on BOTTOM (solid shape): 138.67,30.85 137.84,28.83 135.82,28 126.24,28 124.23,28.83 123.39,30.85 123.39,33.15 124.03,33.15 124.03,30.85 124.67,29.28 126.24,28.63 135.82,28.63 137.39,29.28 138.04,30.85 138.04,38.1 138.67,38.1
GND on BOTTOM (solid shape): 70.17,30.85 69.34,28.83 67.32,28 57.74,28 55.72,28.83 54.89,30.85 54.89,32.96 54.89,33.21 55.53,33.21 55.52,30.85 56.17,29.28 57.74,28.63 67.32,28.63 68.89,29.28 69.54,30.85 69.54,38.1 70.17,38.1
GND on BOTTOM (solid shape): 22.51,30.85 23.16,29.28 24.72,28.63 33.84,28.63 35.41,29.28 36.06,30.85 36.06,33.95 36.69,33.95 36.69,30.85 35.86,28.83 33.84,28 24.72,28 22.71,28.83 21.87,30.85 21.87,40.01 7.5,40.01 7.5,40.64 22.51,40.64
GND on BOTTOM (solid shape): 91.01,30.85 91.66,29.28 93.22,28.63 102.34,28.63 103.91,29.28 104.56,30.85 104.56,33.78 105.19,33.78 105.19,30.85 104.36,28.83 102.34,28 93.22,28 91.21,28.83 90.37,30.85 90.37,40.01 75.99,40.01 75.99,40.64 91.01,40.64
GND on BOTTOM (solid shape): 159.51,30.85 160.16,29.28 161.72,28.63 170.84,28.63 172.41,29.28 173.06,30.85 173.06,33.59 173.69,33.59 173.69,30.85 172.86,28.83 170.84,28 161.72,28 159.71,28.83 158.87,30.85 158.87,40.01 144.59,40.01 144.59,40.64 159.51,40.64
GND on BOTTOM (solid shape): 207.17,30.85 206.34,28.83 204.32,28 194.74,28 192.72,28.83 191.89,30.85 191.89,32.96 191.89,33.14 192.53,33.14 192.52,30.85 193.17,29.28 194.74,28.63 204.32,28.63 205.89,29.28 206.54,30.85 206.54,38.23 207.17,38.23
GND on BOTTOM (solid shape): 228.01,30.85 228.66,29.28 230.22,28.63 239.34,28.63 240.91,29.28 241.56,30.85 241.56,33.72 242.19,33.72 242.19,30.85 241.36,28.83 239.34,28 230.22,28 228.21,28.83 227.37,30.85 227.37,40.01 213.11,40.01 213.11,40.64 228.01,40.64
GND on BOTTOM (solid shape): outline of 98 points within 1.02,1.02 261.03,33.41
GND on TOP: 183.3,33.98 183.3,43.11 183.41,43.22 184.69,43.22 184.83,43.08 184.83,33.98 184.73,33.89 183.39,33.89
GND on TOP: 46.3,33.98 46.3,43.11 46.41,43.22 47.69,43.22 47.83,43.08 47.83,33.98 47.73,33.89 46.39,33.89
GND on TOP: 190.92,33.98 190.92,43.11 191.03,43.22 192.31,43.22 192.45,43.08 192.45,33.98 192.35,33.89 191.01,33.89
GND on TOP: 114.8,33.98 114.8,43.11 114.91,43.22 116.19,43.22 116.33,43.08 116.33,33.98 116.23,33.89 114.9,33.89
GND on TOP: 53.92,33.98 53.92,43.11 54.03,43.22 55.31,43.22 55.45,43.08 55.45,33.98 55.35,33.89 54.01,33.89
GND on TOP: 251.8,33.98 251.8,43.11 251.91,43.22 253.19,43.22 253.33,43.08 253.33,33.98 253.23,33.89 251.9,33.89
GND on TOP: 259.42,33.98 259.42,43.11 259.53,43.22 260.81,43.22 260.95,43.08 260.95,33.98 260.85,33.89 259.52,33.89
GND on TOP: 122.42,33.98 122.42,43.11 122.53,43.22 123.81,43.22 123.95,43.08 123.95,33.98 123.85,33.89 122.52,33.89
GND on TOP: 16.64,19.05 16.64,13.84 15.62,12.83 12.57,12.83 12.06,12.32 12.06,3.43 12.7,2.79 25.27,2.79 25.65,3.17 25.65,13.97 29.21,17.53 33.53,17.53 33.78,17.78 33.78,18.92 33.02,19.68 17.27,19.68
GND on BOTTOM: 16.64,19.05 16.64,13.84 15.62,12.83 12.57,12.83 12.06,12.32 12.06,3.43 12.7,2.79 25.27,2.79 25.65,3.17 25.65,13.97 29.21,17.53 31.62,17.53 32.89,18.8 32.89,19.43 32.64,19.68 17.27,19.68
GND on G2: outline of 124 points within 1.02,1.02 261.03,43.44
VCC_12P_FAN1 on TOP (solid shape): 187.37,42.5 187.37,34.62 187.39,34.6 188.36,34.6 188.38,34.62 188.38,42.56 188.52,42.7 189.76,42.7 189.91,42.56 189.91,33.78 189.36,33.23 189.36,30.61 194.64,25.32 198.17,25.32 198.17,23.72 198.04,23.6 189.95,23.6 185.42,28.13 185.42,30.62 185.44,30.71 185.45,30.8 185.45,32.9 185.42,32.9 185.42,34.25 185.84,34.67 185.84,42.52 186.02,42.71 187.16,42.71
VCC_12P_FAN2 on TOP (solid shape): 118.87,42.63 118.87,34.62 118.88,34.61 119.87,34.61 119.88,34.62 119.88,42.49 120.07,42.67 121.23,42.67 121.41,42.5 121.41,33.53 120.9,33.03 120.9,30.48 126.06,25.32 127.29,25.32 127.39,25.31 127.49,25.32 128.64,25.32 128.64,23.72 128.51,23.6 120.89,23.6 116.97,27.52 116.97,34.3 117.34,34.67 117.34,42.64 117.42,42.72 118.77,42.72
VCC_12P_FAN3 on TOP: 52.37,23.6 48.51,27.46 48.51,34.34 48.84,34.67 48.84,42.45 49.07,42.67 50.21,42.67 50.37,42.52 50.37,34.62 50.39,34.6 51.36,34.6 51.38,34.62 51.38,42.48 51.57,42.67 52.63,42.67 52.91,42.4 52.91,33.53 52.32,32.95 52.32,30.1 57.1,25.32 60.12,25.32 60.12,23.72 59.99,23.6
VCC_12P_FAN4 on TOP (solid shape): 255.87,42.5 255.87,34.62 255.87,34.62 256.88,34.62 256.88,34.62 256.88,42.45 257.1,42.67 258.21,42.67 258.41,42.47 258.41,33.62 257.81,33.02 257.81,30.61 259.59,28.83 259.59,17.02 251.98,9.41 251.16,9.41 250.82,9.07 250.82,8.7 250.82,8.7 250.82,7.63 249.21,7.63 249.09,7.76 249.09,15.38 249.33,15.62 251.27,15.62 255.91,20.26 255.91,26.8 254.34,28.36 254.34,30.32 254.36,30.33 254.36,32.38 254.34,32.39 254.34,42.39 254.63,42.68 255.68,42.68
VCC_CL_FAN1 on TOP (solid shape): 201.93,25.17 201.93,21.03 201.75,20.85 200.2,20.85 200.1,20.95 200.1,22.63 200.36,22.89 200.36,25.32 201.78,25.32
VCC_CL_FAN2 on TOP (solid shape): 132.4,25.17 132.4,21.03 132.22,20.85 130.67,20.85 130.57,20.95 130.57,22.63 130.82,22.89 130.82,25.32 132.25,25.32
VCC_CL_FAN3 on TOP: 62.31,25.32 63.73,25.32 63.88,25.17 63.88,21.03 63.7,20.85 62.15,20.85 62.05,20.95 62.05,22.63 62.31,22.89
VCC_CL_FAN4 on TOP (solid shape): 248.37,5.45 250.81,5.45 250.81,4.03 250.66,3.87 246.52,3.87 246.34,4.05 246.34,5.6 246.44,5.7 248.12,5.7
VDD12V on TOP (solid shape): 129.93,22.61 129.93,19.65 129.67,19.38 127,19.38 126.81,19.57 126.81,21.16 126.63,21.34 124.98,21.34 124.78,21.54 124.78,22.73 124.88,22.83 129.71,22.83
VDD12V on TOP (solid shape): 199.47,22.61 199.47,19.74 199.24,19.51 196.55,19.51 196.34,19.71 196.34,21.16 196.16,21.34 194.51,21.34 194.31,21.54 194.31,22.73 194.41,22.83 199.24,22.83
VDD12V on TOP (solid shape): 248.32,11.39 248.32,6.57 248.09,6.34 245.2,6.34 244.93,6.6 244.93,9.12 245.28,9.46 246.65,9.46 246.82,9.64 246.82,11.29 247.03,11.49 248.22,11.49
VDD12V on TOP: 155,27.69 163.96,27.69 164.47,27.18 164.47,25.02 163.83,24.38 155.26,24.38 154.62,25.02 154.62,27.3
VDD12V on TOP: 56.36,22.83 61.19,22.83 61.42,22.61 61.42,19.76 61.19,19.53 58.47,19.53 58.29,19.71 58.29,21.16 58.12,21.34 56.46,21.34 56.26,21.54 56.26,22.73
VDD12V on TOP: 2.41,3.17 2.41,14.99 3.56,16.13 10.77,16.13 13.64,19 13.64,23.8 14.48,24.64 30.35,24.64 32.77,22.23 32.77,20.83 32.51,20.57 17.27,20.57 16.13,19.43 16.13,14.35 15.11,13.34 12.19,13.34 11.43,12.57 11.43,3.56 10.29,2.41 3.17,2.41
VDD12V on BOTTOM: 2.41,3.17 2.41,14.99 3.56,16.13 10.77,16.13 13.64,19 13.64,23.8 14.48,24.64 32.26,24.64 32.77,24.13 32.77,20.83 32.51,20.57 17.27,20.57 16.13,19.43 16.13,14.35 15.11,13.34 12.19,13.34 11.43,12.57 11.43,3.56 10.29,2.41 3.17,2.41
VDD12V on BOTTOM: 155,27.69 163.96,27.69 164.47,27.18 164.47,25.02 164.08,24.64 155,24.64 154.62,25.02 154.62,27.3
VDD12V on V3: 135.69,23.88 144.16,32.35 155.8,32.35 160.59,27.57 184.84,27.57 189.34,23.06 243.59,23.06 248.77,17.88 248.77,7.09 247.8,6.12 235.71,6.12 230.91,10.92 162.38,10.92 159.11,14.2 159.11,21.56 156.95,23.72 146.41,23.72 141.78,19.1 141.78,14.48 139.62,12.32 62.1,12.32 57.99,8.2 24.97,8.2 21.15,4.38 6.99,4.38 6.1,5.27 6.1,12.83 7.75,14.48 10.16,14.48 13.84,18.16 13.84,22.99 14.73,23.88
(no net) on TOP: 120.89,23.6 116.97,27.52 116.97,34.3 117.34,34.67 117.34,42.64 117.42,42.72 118.77,42.72 118.87,42.63 118.87,34.62 118.88,34.61 119.87,34.61 119.88,34.62 119.88,42.49 120.07,42.67 121.23,42.67 121.41,42.5 121.41,33.53 120.9,33.03 120.9,30.48 126.06,25.32 128.64,25.32 128.64,23.72 128.51,23.6
(no net) on TOP: 248.32,11.39 248.32,6.57 248.09,6.34 245.2,6.34 244.93,6.6 244.93,9.12 245.28,9.46 246.65,9.46 246.82,9.64 246.82,11.29 247.03,11.49 248.22,11.49
(no net) on TOP: 200.36,25.32 201.78,25.32 201.93,25.17 201.93,21.03 201.75,20.85 200.2,20.85 200.1,20.95 200.1,22.63 200.36,22.89
(no net) on TOP: 130.82,25.32 132.25,25.32 132.4,25.17 132.4,21.03 132.22,20.85 130.67,20.85 130.57,20.95 130.57,22.63 130.82,22.89
(no net) on TOP: 250.81,5.45 250.81,4.03 250.66,3.87 246.52,3.87 246.34,4.05 246.34,5.6 246.44,5.7 248.12,5.7 248.37,5.45
(no net) on TOP: 124.88,22.83 129.71,22.83 129.93,22.61 129.93,19.65 129.67,19.38 127,19.38 126.81,19.57 126.81,21.16 126.63,21.34 124.98,21.34 124.78,21.54 124.78,22.73
(no net) on TOP: 249.09,15.38 249.33,15.62 251.27,15.62 255.91,20.26 255.91,26.8 254.34,28.36 254.34,42.39 254.63,42.68 255.68,42.68 255.87,42.5 255.87,34.62 255.87,34.62 256.88,34.62 256.88,34.62 256.88,42.45 257.1,42.67 258.21,42.67 258.41,42.47 258.41,33.62 257.81,33.02 257.81,30.61 259.59,28.83 259.59,17.02 251.98,9.41 251.16,9.41 250.82,9.07 250.82,7.63 249.21,7.63 249.09,7.76
(no net) on TOP: 189.95,23.6 185.42,28.13 185.42,34.25 185.84,34.67 185.84,42.52 186.02,42.71 187.16,42.71 187.37,42.5 187.37,34.62 187.39,34.6 188.36,34.6 188.38,34.62 188.38,42.56 188.52,42.7 189.76,42.7 189.91,42.56 189.91,33.78 189.36,33.23 189.36,30.61 194.64,25.32 198.17,25.32 198.17,23.72 198.04,23.6
(no net) on TOP: 194.41,22.83 199.24,22.83 199.47,22.61 199.47,19.74 199.24,19.51 196.55,19.51 196.34,19.71 196.34,21.16 196.16,21.34 194.51,21.34 194.31,21.54 194.31,22.73
VSTB_3V3 on BOTTOM: 59.47,11.68 53.43,11.68 49.18,15.94 36.29,15.94 34.64,14.29 34.64,6.6 33.62,5.59 27.21,5.59 26.32,6.48 26.32,14 28.64,16.32 30.86,16.32 34.42,19.88 52.77,19.88 56.13,16.51 59.94,16.51 60.45,16 60.45,11.81 60.37,11.73 59.52,11.73
VSTB_3V3 on V3: outline of 135 points within 1.52,1.52 260.52,42.93
N66403123 on TOP (solid shape): outline of 228 points within 111.52,6.64 118.53,13.65
N66403123 on BOTTOM (solid shape): outline of 228 points within 111.52,6.64 118.53,13.65

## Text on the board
User.Comments: CR_U4_3 | CR_U6-NEW2_1 | CR_U6_2 | CR_U4_2 | CR_U6_3 | CR_U6-NEW2_2 | CR_U6-NEW3_1 | CR_U6_1 | CR_U4_1 | STB V2
Ref Des/Silkscreen Top: A | P/N:142000001617A REV:0C
PLACE_BOUND_TOP: TOP (COMPONENT_SIDE)                      1
DISPLAY_TOP: G2  (GND_LAYER_2)                         2
PAGE_OUTLINE: V3  (VCC_LAYER_3)                         3
User.5: BOT (SOLDER_SIDE)                         4
User.6: SST (SILKSCREEN_TOP)                      5
User.7: SSB (SILKSCREEN_BOTTOM)                   6
User.8: SMT (SOLDER_MASK_TOP)                     7
User.9: SMB (SOLDER_MASK_BOTTOM)                   8
User.10: DRILL(FINISH HOLE SIZE LIST)               9
User.11: PMT (PASTE_MASK_TOP)                     10
User.12: PMB (PASTE_MASK_BOTTOM)                  11
User.13: DIM (BOARD_DIMENSION)                    12
User.14: FIGURE | SIZE | 10.0 | 12.0 | 24.0 | 63.0 | 118.0 | 125.0 | TOLERANCE | +3.0/-3.0 | +2.0/-2.0 | +3.0/-0.0 | ALL UNITS ARE IN MILS | PLATED | NON-PLATED | QTY | 92 | 519 | 33 | 4 | 1 | 3 | DRILL CHART: TOP to BOTTOM
